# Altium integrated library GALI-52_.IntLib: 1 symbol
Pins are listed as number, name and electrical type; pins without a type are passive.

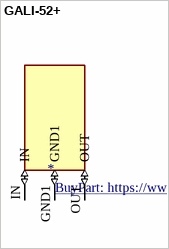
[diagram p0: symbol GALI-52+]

## GALI-52+
designator ?
RF Amplifier SMT Low Noise Amplifier, DC - 2000 MHz, 50; MF: Mini-Circuits; MP: GALI-52+
footprint GALI-52+
pins: GND1 (io), IN (io), OUT (io)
